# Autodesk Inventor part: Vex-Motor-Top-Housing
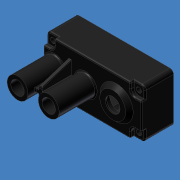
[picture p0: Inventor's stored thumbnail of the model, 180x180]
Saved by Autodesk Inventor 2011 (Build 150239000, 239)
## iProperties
Created: 2007-08
Part Number: Vex-Motor-Top-Housing
Material: Alloy Steel
Document SubType Name: Modeling
Density: 7.85 g/cm^3
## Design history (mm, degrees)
feature "Base1"
body "Solid1"
